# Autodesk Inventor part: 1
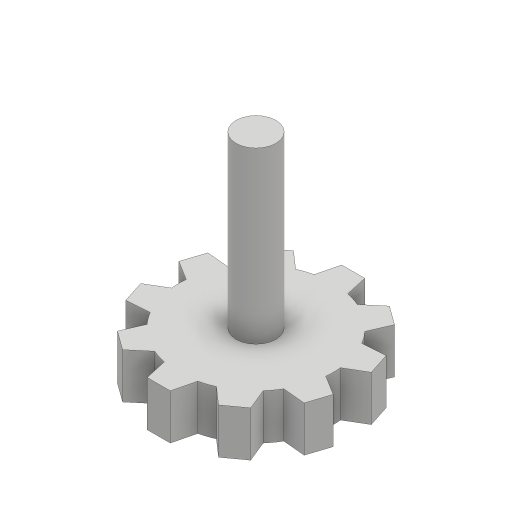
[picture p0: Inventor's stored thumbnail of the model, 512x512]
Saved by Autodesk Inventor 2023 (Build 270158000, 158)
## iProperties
Created: 2017-05
Part Number: 1
Material: Generic
Document SubType Name: Modeling
Designer: CADCIM 00
Density: 1 g/cm^3
Appearance: Default
Author: CADCIM 00
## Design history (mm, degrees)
sketch "Sketch1"
  geometry: L1 (-3.765, 16.614)-(-2.561, 21.495); L2 (-2.561, 21.495)-(2.518, 21.495); L3 (2.518, 21.495)-(3.613, 16.648); L4 (-12.811, 11.228)-(-14.706, 15.884); L5 (-14.706, 15.884)-(-10.598, 18.87); L6 (-10.598, 18.87)-(-6.862, 15.592); L7 (-16.964, 1.554)-(-21.234, 4.206); L8 (-21.234, 4.206)-(-19.665, 9.037); L9 (-19.665, 9.037)-(-14.716, 8.581); L10 (-14.637, -8.714)-(-19.651, -9.078); L11 (-19.651, -9.078)-(-21.221, -4.248); L12 (-21.221, -4.248)-(-16.949, -1.708); L13 (-6.72, -15.654)-(-10.562, -18.895); L14 (-10.562, -18.895)-(-14.671, -15.91); L15 (-14.671, -15.91)-(-12.708, -11.344); L16 (3.765, -16.614)-(2.561, -21.495); L17 (2.561, -21.495)-(-2.518, -21.495); L18 (-2.518, -21.495)-(-3.613, -16.648); L19 (12.811, -11.228)-(14.706, -15.884); L20 (14.706, -15.884)-(10.598, -18.87); L21 (10.598, -18.87)-(6.862, -15.592); L22 (16.964, -1.554)-(21.234, -4.206); L23 (21.234, -4.206)-(19.665, -9.037); L24 (19.665, -9.037)-(14.716, -8.581); L25 (14.637, 8.714)-(19.651, 9.078); L26 (19.651, 9.078)-(21.221, 4.248); L27 (21.221, 4.248)-(16.949, 1.708); L28 (6.72, 15.654)-(10.562, 18.895); L29 (10.562, 18.895)-(14.671, 15.91); L30 (14.671, 15.91)-(12.708, 11.344); A1 r 17.035 centre (0, 0) between (-3.765, 16.614) and (-6.862, 15.592); A2 r 17.035 centre (0, 0) between (-12.811, 11.228) and (-14.716, 8.581); A3 r 17.035 centre (0, 0) between (-16.964, 1.554) and (-16.949, -1.708); A4 r 17.035 centre (0, 0) between (-14.637, -8.714) and (-12.708, -11.344); A5 r 17.035 centre (0, 0) between (-6.72, -15.654) and (-3.613, -16.648); A6 r 17.035 centre (0, 0) between (3.765, -16.614) and (6.862, -15.592); A7 r 17.035 centre (0, 0) between (12.811, -11.228) and (14.716, -8.581); A8 r 17.035 centre (0, 0) between (16.964, -1.554) and (16.949, 1.708); A9 r 17.035 centre (0, 0) between (14.637, 8.714) and (12.708, 11.344); A10 r 17.035 centre (0, 0) between (6.72, 15.654) and (3.613, 16.648); 1 further point
  constraints: 60 end point, 20 point on circle, 10 centre point, 1 coincident, 1 horizontal, 71 other
  dimensions: "d2" = 360 deg dimension on A1.centre L1.start (derived)
extrude "Extrusion1" new body sketch "Sketch1" distance "d4" = 10; taper "d5" = 0 deg
sketch "Sketch2"
  geometry: C1 r 4.406 at (0, 0); 1 further point
  constraints: 1 centre point, 1 coincident
extrude "Extrusion2" join sketch "Sketch2" distance "d6" = 37.5; taper "d7" = 0 deg
body "Solid1"
